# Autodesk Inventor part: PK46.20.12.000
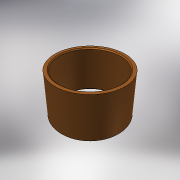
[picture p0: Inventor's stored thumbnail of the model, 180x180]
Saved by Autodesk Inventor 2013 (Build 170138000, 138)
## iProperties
Created: 2012-02
Part Number: PK46.20.12.000
Material: Bronze, Soft Tin
Document SubType Name: Modeling
Designer: tedescj
Mass: 36.3652 g
Surface Area: 44.6933 cm^2
Volume: 4.09795 cm^3
Density: 8.874 g/cm^3
Author: tedescj
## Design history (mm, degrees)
derived "PK46.20.10.000.ipt"
feature "PK46.20.12.000::PK46.20.10.000.ipt" dims "d0" = 10
tag "TaggingFeature1"
body "Solid1"
